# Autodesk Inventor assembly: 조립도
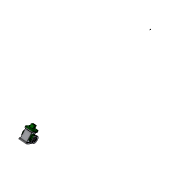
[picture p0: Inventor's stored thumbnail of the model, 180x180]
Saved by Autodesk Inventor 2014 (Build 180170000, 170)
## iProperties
Created: 2017-08
Part Number: 조립도
Document SubType Name: Assembly
Designer: user
Author: user
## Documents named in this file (18)
- C:\Users\user\Desktop\470808V1003\조립도.iam
- C:\Users\user\Desktop\470808V1003\본체.ipt
- C:\Users\user\Desktop\470808V1003\E-링.ipt
- C:\Users\user\Desktop\470808V1003\V-벨트풀리.ipt
- C:\Users\user\Desktop\470808V1003\덮개.ipt
- C:\Users\user\Desktop\470808V1003\뒤커버.ipt
- C:\Users\user\Desktop\470808V1003\링크.ipt
- C:\Users\user\Desktop\470808V1003\베어링 17 x 40 x 12.ipt
- C:\Users\user\Desktop\470808V1003\볼트 M4 x 8.ipt
- C:\Users\user\Desktop\470808V1003\볼트 M4 x 10.ipt
- C:\Users\user\Desktop\470808V1003\슬라이더.ipt
- C:\Users\user\Desktop\470808V1003\앞커버.ipt
- C:\Users\user\Desktop\470808V1003\오일 실 17 30 8.ipt
- C:\Users\user\Desktop\470808V1003\와셔 4x16.ipt
- C:\Users\user\Desktop\470808V1003\클레비스 핀 6 x 22.ipt
- 클레비스 핀 6 x 22.ipt
- C:\Users\user\Desktop\470808V1003\키 4 x 4 x 12.ipt
- C:\Users\user\Desktop\470808V1003\편심축.ipt
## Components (2 placed, 2 different names)
1. E-링:1 — Mate:18
2. V-벨트풀리:1 — Mate:12, Mate:13, Insert:6, Mate:23
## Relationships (5: Mate 4, Insert 1)
- Mate:12: V-벨트풀리:1
- Mate:13: V-벨트풀리:1
- Insert:6: V-벨트풀리:1
- Mate:18: E-링:1
- Mate:23: V-벨트풀리:1
